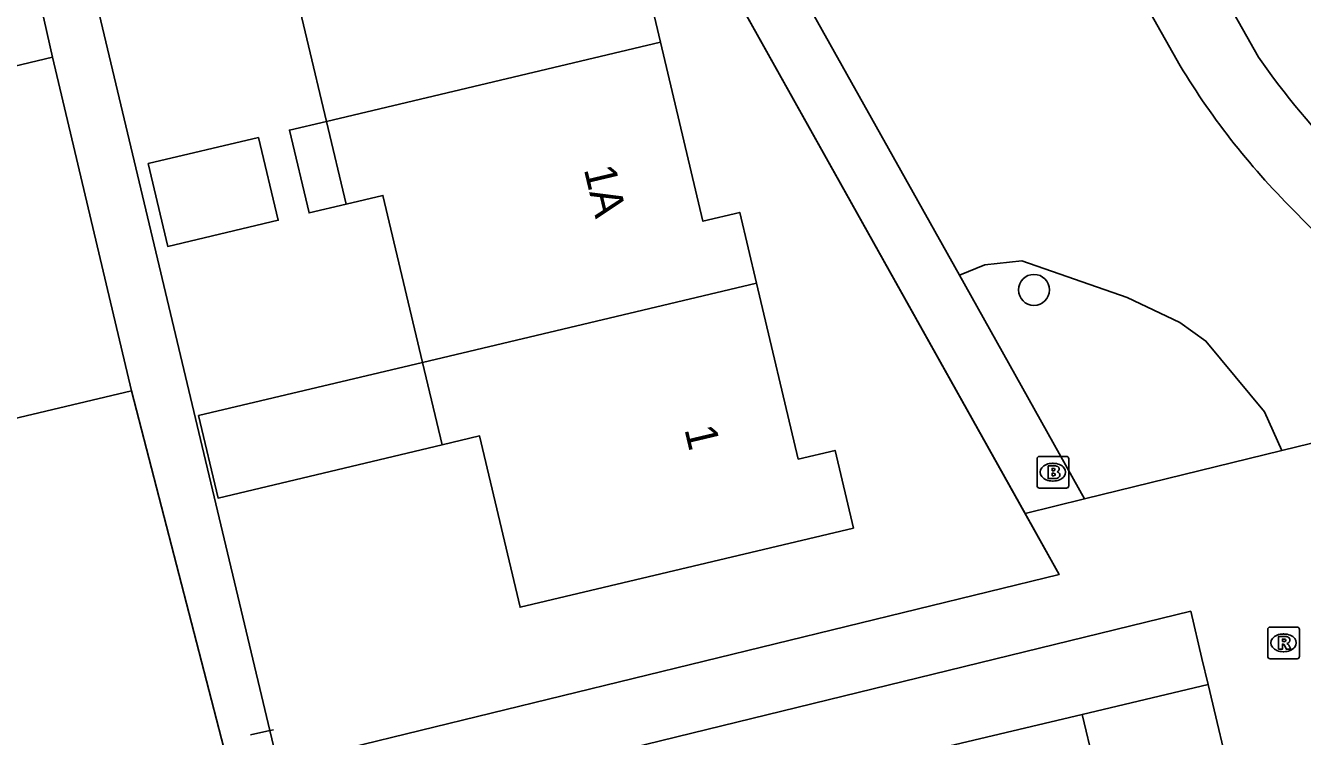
# Model space of a CAD drawing. Extents: x 158038 to 159242, y 380133 to 381214.
# Drawn here: x 158790.59 to 158830.89, y 380556.14 to 380578.57 of the extents above; entities that cross this region are included whole.
import ezdxf

# ---------------------------------------------------------------- set-up
doc = ezdxf.new("R2010")
doc.units = 0
for name, color, linetype in [('IMGEO_Boom', 7, 'Continuous'), ('IMGEO_Brandkraan', 7, 'Continuous'), ('IMGEO_Groenvoorziening', 7, 'Continuous'), ('IMGEO_Hek', 7, 'Continuous'), ('IMGEO_Pand', 7, 'Continuous'), ('IMGEO_Pand_nummerreeks', 7, 'Continuous'), ('IMGEO_Rioolput', 7, 'Continuous'), ('IMGEO_Voetpad_open', 7, 'Continuous')]:
    doc.layers.add(name, color=color, linetype=linetype)

msp = doc.modelspace()

# ---------------------------------------------------------------- linework, layer by layer
at = {"layer": 'IMGEO_Boom'}
msp.add_circle((158822.418, 380570.228), 0.489, dxfattribs=at)
at = {"layer": 'IMGEO_Brandkraan'}
for p, q in [((158822.514, 380564.05), (158822.514, 380564.902)), ((158822.589, 380564.976), (158823.441, 380564.976)), ((158823.002, 380564.756), (158823.027, 380564.756)), ((158823.515, 380564.902), (158823.515, 380564.05)), ((158823.441, 380563.976), (158822.589, 380563.976)), ((158823.025, 380564.196), (158823, 380564.196))]:
    msp.add_line(p, q, dxfattribs=at)
for points in [[(158822.514, 380564.05), (158822.514, 380564.902)], [(158822.589, 380564.976), (158823.441, 380564.976)], [(158822.862, 380564.676), (158822.862, 380564.276), (158823.075, 380564.276)], [(158823.093, 380564.676), (158822.862, 380564.676)], [(158823.515, 380564.902), (158823.515, 380564.05)], [(158823.041, 380564.595), (158822.987, 380564.595), (158822.987, 380564.519)], [(158822.987, 380564.519), (158823.04, 380564.519)], [(158823.049, 380564.443), (158822.987, 380564.443), (158822.987, 380564.362)], [(158822.987, 380564.362), (158823.049, 380564.362)], [(158823.441, 380563.976), (158822.589, 380563.976)]]:
    msp.add_lwpolyline(points, dxfattribs=at)
for centre, radius, start, end in [((158822.591, 380564.9), 0.0765, 91.552, 178.448), ((158822.591, 380564.9), 0.0765, 91.552, 178.448), ((158823.097, 380564.531), 0.145, 59.4692, 91.5367), ((158823.122, 380564.578), 0.0922, 285.5137, 58.1501), ((158823.439, 380564.9), 0.0765, 1.552, 88.448), ((158823.439, 380564.9), 0.0765, 1.552, 88.448), ((158823.042, 380564.557), 0.0379, 267.8285, 90.9355), ((158823.05, 380564.402), 0.0404, 269.8759, 90.5077), ((158823.081, 380564.527), 0.251, 268.6676, 293.5347), ((158823.127, 380564.386), 0.105, 301.3115, 78.989), ((158822.591, 380564.052), 0.0765, 181.552, 268.448), ((158822.591, 380564.052), 0.0765, 181.552, 268.448), ((158823.439, 380564.052), 0.0765, 271.552, 358.448), ((158823.439, 380564.052), 0.0765, 271.552, 358.448)]:
    msp.add_arc(centre, radius, start, end, dxfattribs=at)
for centre, major_axis, ratio, start_param, end_param in [((158823.001, 380564.476), (-0.387, 0.002), 0.722429, 4.712389, 7.853982), ((158823.026, 380564.476), (-0.39, 0.002), 0.717154, 1.570796, 4.712389)]:
    msp.add_ellipse(centre, major_axis=major_axis, ratio=ratio, start_param=start_param, end_param=end_param, dxfattribs=at)
at = {"layer": 'IMGEO_Groenvoorziening'}
for points in [[(158820.064, 380570.69), (158820.864, 380571.023), (158822.032, 380571.149), (158825.356, 380569.99), (158827.018, 380569.201), (158827.843, 380568.615), (158829.693, 380566.379), (158830.239, 380565.156)], [(158827.913, 380557.776), (158823.94, 380556.835)]]:
    msp.add_lwpolyline(points, dxfattribs=at)
at = {"layer": 'IMGEO_Hek'}
for points in [[(158808.541, 380587.487), (158823.212, 380561.244)], [(158795.906, 380566.394), (158791.819, 380583.549)], [(158797.088, 380554.845), (158793.932, 380567.048)], [(158798.304, 380556.328), (158795.906, 380566.394)], [(158823.212, 380561.244), (158798.566, 380555.227), (158798.304, 380556.328)], [(158798.304, 380556.328), (158797.692, 380556.192)], [(158798.414, 380556.352), (158798.304, 380556.328)]]:
    msp.add_lwpolyline(points, dxfattribs=at)
at = {"layer": 'IMGEO_Pand'}
for points in [[(158800.086, 380575.546), (158798.848, 380580.768), (158797.682, 380580.491), (158797.023, 380583.274), (158807.568, 380585.775), (158808.926, 380580.045), (158810.09, 380580.321), (158810.629, 380578.047)], [(158800.086, 380575.546), (158810.629, 380578.047)], [(158810.629, 380578.047), (158811.969, 380572.396), (158813.132, 380572.672), (158813.662, 380570.437)], [(158783.7, 380574.492), (158789.292, 380575.818), (158789.013, 380576.998), (158791.436, 380577.573)], [(158791.436, 380577.573), (158793.932, 380567.048)], [(158800.086, 380575.546), (158798.918, 380575.269), (158799.538, 380572.656), (158800.706, 380572.933)], [(158800.706, 380572.933), (158800.086, 380575.546)], [(158797.945, 380575.038), (158794.462, 380574.212), (158795.081, 380571.602), (158798.565, 380572.426), (158797.945, 380575.038)], [(158803.118, 380567.937), (158801.868, 380573.208), (158800.706, 380572.933)], [(158803.118, 380567.937), (158813.662, 380570.437)], [(158813.662, 380570.437), (158814.978, 380564.888), (158816.139, 380565.163), (158816.72, 380562.712), (158806.199, 380560.217), (158804.918, 380565.619), (158803.735, 380565.338)], [(158803.735, 380565.338), (158796.668, 380563.659), (158796.052, 380566.262), (158803.118, 380567.937)], [(158803.118, 380567.937), (158803.735, 380565.338)], [(158793.932, 380567.048), (158788.512, 380565.763), (158788.791, 380564.588), (158786.195, 380563.972)], [(158823.94, 380556.835), (158813.907, 380554.456)], [(158823.94, 380556.835), (158824.67, 380553.756), (158823.366, 380553.446), (158824.665, 380547.968), (158821.912, 380547.315)]]:
    msp.add_lwpolyline(points, dxfattribs=at)
at = {"layer": 'IMGEO_Rioolput'}
for p, q in [((158829.795, 380558.665), (158829.795, 380559.517)), ((158829.87, 380559.591), (158830.722, 380559.591)), ((158830.796, 380559.517), (158830.796, 380558.665)), ((158830.283, 380559.371), (158830.308, 380559.371)), ((158830.306, 380558.811), (158830.281, 380558.811)), ((158830.722, 380558.591), (158829.87, 380558.591))]:
    msp.add_line(p, q, dxfattribs=at)
for points in [[(158829.795, 380558.665), (158829.795, 380559.517)], [(158829.87, 380559.591), (158830.722, 380559.591)], [(158830.796, 380559.517), (158830.796, 380558.665)], [(158830.384, 380559.289), (158830.132, 380559.291), (158830.132, 380558.891)], [(158830.132, 380558.891), (158830.256, 380558.891), (158830.256, 380559.053), (158830.267, 380559.053)], [(158830.31, 380559.21), (158830.256, 380559.21), (158830.256, 380559.129)], [(158830.256, 380559.129), (158830.308, 380559.129)], [(158830.314, 380559.024), (158830.385, 380558.891), (158830.525, 380558.891), (158830.46, 380559.017)], [(158830.722, 380558.591), (158829.87, 380558.591)]]:
    msp.add_lwpolyline(points, dxfattribs=at)
for centre, radius, start, end in [((158829.872, 380559.515), 0.0765, 91.552, 178.448), ((158829.872, 380559.515), 0.0765, 91.552, 178.448), ((158830.72, 380559.515), 0.0765, 1.552, 88.448), ((158830.72, 380559.515), 0.0765, 1.552, 88.448), ((158830.266, 380559), 0.0533, 26.0293, 88.6989), ((158830.292, 380559.318), 0.19, 274.7715, 282.9687), ((158830.316, 380559.114), 0.0964, 77.0061, 93.1865), ((158830.33, 380559.171), 0.0378, 276.6634, 79.6772), ((158830.383, 380559.179), 0.109, 350.3612, 89.416), ((158830.381, 380559.179), 0.112, 277.5842, 350.9817), ((158830.365, 380558.964), 0.108, 29.5134, 73.7905), ((158829.872, 380558.667), 0.0765, 181.552, 268.448), ((158829.872, 380558.667), 0.0765, 181.552, 268.448), ((158830.72, 380558.667), 0.0765, 271.552, 358.448), ((158830.72, 380558.667), 0.0765, 271.552, 358.448)]:
    msp.add_arc(centre, radius, start, end, dxfattribs=at)
for centre, major_axis, ratio, start_param, end_param in [((158830.282, 380559.091), (-0.387, 0.002), 0.722429, 4.712389, 7.853982), ((158830.307, 380559.091), (-0.39, 0.002), 0.717154, 1.570796, 4.712389)]:
    msp.add_ellipse(centre, major_axis=major_axis, ratio=ratio, start_param=start_param, end_param=end_param, dxfattribs=at)
at = {"layer": 'IMGEO_Voetpad_open'}
for points in [[(158820.064, 380570.69), (158806.385, 380595.117)], [(158827.03, 380577.302), (158820.147, 380589.495), (158819.92, 380590.218), (158819.884, 380591.912)], [(158822.35, 380590.244), (158829.502, 380577.574)], [(158822.135, 380563.17), (158808.541, 380587.487)], [(158789.597, 380585.709), (158791.436, 380577.573)], [(158791.819, 380583.549), (158795.906, 380566.394), (158798.304, 380556.328), (158798.566, 380555.227)], [(158824.017, 380563.631), (158820.064, 380570.69)], [(158793.932, 380567.048), (158797.088, 380554.845)], [(158836.022, 380566.573), (158835.279, 380566.391), (158830.239, 380565.156)], [(158830.239, 380565.156), (158824.017, 380563.631)], [(158822.135, 380563.17), (158824.017, 380563.631)], [(158798.566, 380555.227), (158823.212, 380561.244), (158822.135, 380563.17)], [(158799.053, 380553.165), (158799.189, 380553.198), (158827.366, 380560.088), (158827.719, 380558.594), (158827.913, 380557.776)], [(158827.913, 380557.776), (158830.214, 380548.061)]]:
    msp.add_lwpolyline(points, dxfattribs=at)
for centre, radius, start, end in [((158850.727, 380592.409), 25.896, 214.9509, 234.2754), ((158847.421, 380589.634), 23.83, 211.1642, 225.5932), ((158846.278, 380587.187), 21.301, 223.1823, 239.3215)]:
    msp.add_arc(centre, radius, start, end, dxfattribs=at)

# ---------------------------------------------------------------- texts
at = {"layer": 'IMGEO_Pand_nummerreeks'}
for s, rotation, p in [('1A', 283.3406, (158808.207, 380574.041)), ('1', 283.3483, (158811.381, 380565.836))]:
    msp.add_text(s, height=1, rotation=rotation, dxfattribs=at).set_placement(p)

doc.saveas('drawing.dxf')
